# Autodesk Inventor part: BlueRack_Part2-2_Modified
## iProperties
Shininess: 64.0
Length Units: 11272
Angle Units: 11279
Time Units: 11290
Mass Units: 11286
Length Display Precision: 3
Angle Display Precision: 2
Compacted: True
Part Number: BlueRack_Part2-2_Modified
Document SubType Name: Modeling
Created: 2004-12
Designer: John Blackburn
Material: Steel, Mild
Manufacturer: Standard
Standards Organization: Custom
Density: 0.0
Volumn: 0.0
Area: 0.0
PropertySet Name: Model Information
Control State: 0
Master: False
Checked Out: False
Author: John Blackburn
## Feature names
1. Extrusion1
2. Hole3
3. Rectangular Pattern3
4. Hole4
5. Rectangular Pattern4
6. Hole5
7. Rectangular Pattern5
